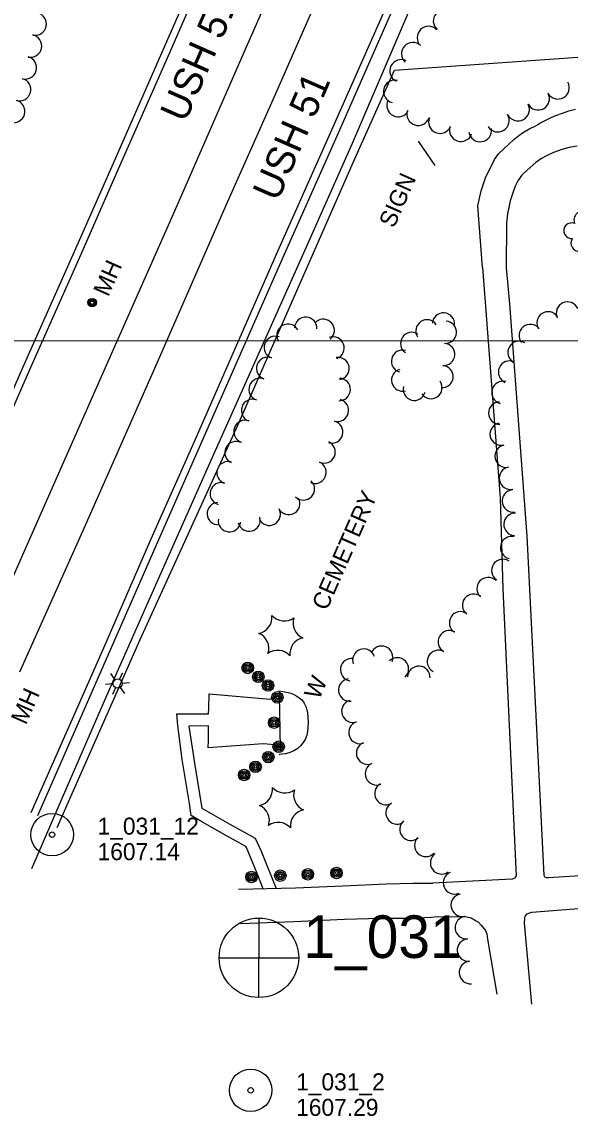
# Model space of a CAD drawing. Extents: x 189384 to 193282, y 256970 to 260388.
# Drawn here: x 190295.2 to 190488.3, y 257237.9 to 257623.7 of the extents above; entities that cross this region are included whole.
import ezdxf

# ---------------------------------------------------------------- set-up
doc = ezdxf.new("R2010")
doc.units = 0
for name, color, linetype in [('E_BMGRD', 7, 'Continuous'), ('E_DRN_Grate', 7, 'Continuous'), ('E_DWY', 7, 'Continuous'), ('E_LAND_Vegetation', 7, 'Continuous'), ('E_MAP_GridLines', 7, 'Continuous'), ('E_MAP_Limits', 7, 'Continuous'), ('E_MAP_PassPoints', 7, 'Continuous'), ('E_MISCPROP', 7, 'Continuous'), ('E_MISCPROP_Railing', 7, 'Continuous'), ('E_PATH_Sidewalk', 7, 'Continuous'), ('E_RDWY', 7, 'Continuous'), ('E_RDWY_Name', 7, 'Continuous')]:
    doc.layers.add(name, color=color, linetype=linetype)

# ---------------------------------------------------------------- blocks, each defined once
blk = doc.blocks.new('PP_8')
at = {"layer": 'E_MAP_PassPoints'}
for radius in [7.5, 0.96]:
    blk.add_circle((0, 0), radius, dxfattribs=at)
blk = doc.blocks.new('PHOTOC')
at = {"layer": 'E_MAP_Limits'}
for p, q in [((0.12, 14.06), (0.06, -13.8)), ((-13.79, 0.03), (14.12, 0.01))]:
    blk.add_line(p, q, dxfattribs=at)
blk.add_circle((0.17, 0.03), 14, dxfattribs=at)
blk = doc.blocks.new('CEM')
at = {"layer": 'E_BMGRD'}
blk.add_text('CEMETERY', height=6, rotation=0.0001, dxfattribs=at).set_placement((-22.99, -3.18))
blk = doc.blocks.new('WAL')
at = {"layer": 'E_MISCPROP_Railing'}
blk.add_text('W', height=6, rotation=360, dxfattribs=at).set_placement((-2.3, -3.01))
blk = doc.blocks.new('POLE')
at = {"layer": 'E_MISCPROP'}
for radius in [2.02, 1.51, 1.01, 0.504]:
    blk.add_circle((0.03, -0.09), radius, dxfattribs=at)
blk = doc.blocks.new('MHO_1')
at = {"layer": 'E_DRN_Grate'}
for centre, radius in [((0.04, -0.06), 1.5), ((0.04, -0.06), 1.22), ((0.04, -0.07), 0.968), ((0.01, -0.08), 0.605)]:
    blk.add_circle(centre, radius, dxfattribs=at)
blk = doc.blocks.new('LTP_11')
at = {"layer": 'E_MISCPROP'}
for p, q in [((-1.64, 0.07), (-4.24, 0.14)), ((-0.8, 1.43), (-2, 3.73)), ((0.9, 1.42), (2.27, 3.65)), ((-0.88, -1.42), (-2.24, -3.61)), ((0.76, -1.47), (2, -3.65)), ((1.64, -0.02), (4.16, -0.09))]:
    blk.add_line(p, q, dxfattribs=at)
blk.add_circle((0, 0), 1.64, dxfattribs=at)
blk = doc.blocks.new('SIGN_8')
at = {"layer": 'E_MISCPROP'}
blk.add_text('SIGN', height=6, rotation=0.0002, dxfattribs=at).set_placement((-9.61, -3.01))
blk = doc.blocks.new('TREE_3')
at = {"layer": 'E_LAND_Vegetation'}
for centre, radius, start, end in [((-1.47, 4.28), 2.78, 1.3945, 209.1675), ((3.57, 2.42), 2.97, 278.4236, 139.6575), ((-4.47, 0.2), 2.78, 78.0715, 279.0825), ((-2.01, -4.2), 2.61, 140.7796, 358.7122), ((3.46, -3.43), 2.97, 196.0744, 79.0477)]:
    blk.add_arc(centre, radius, start, end, dxfattribs=at)
blk = doc.blocks.new('PINEL')
at = {"layer": 'E_LAND_Vegetation'}
for centre, start, end in [((-8.23, 7.26), 275.2112, 0.9761), ((2.17, 10.66), 215.2112, 300.9761), ((10.31, 3.35), 155.2112, 240.9761), ((-10.49, -3.45), 335.2112, 60.9761), ((8.05, -7.36), 95.2112, 180.9761), ((-2.35, -10.75), 35.2112, 120.9761)]:
    blk.add_arc(centre, 5.72, start, end, dxfattribs=at)

msp = doc.modelspace()

# ---------------------------------------------------------------- linework, layer by layer
at = {"layer": 'E_DWY'}
for points in [[(190307.65, 257339.7), (190336.95, 257405.99), (190371.25, 257481.51), (190412.4, 257575.11), (190426.44, 257606.63), (190736.05, 257628.66), (190837.56, 257638.62), (191029.69, 257654.26)], [(190457.48, 257537.03), (190455.79, 257558.86), (190457.06, 257564.15), (190458.56, 257568.63), (190461.68, 257575.18), (190463.17, 257577.14), (190468.54, 257582.25), (190470.23, 257583.55), (190471.59, 257584.56), (190474.12, 257586.03), (190475.84, 257586.81), (190476.63, 257587.3), (190477.72, 257587.94), (190479.51, 257588.94), (190481.22, 257589.77), (190482.91, 257590.5), (190485.63, 257591.48), (190487.88, 257592.34), (190490.23, 257592.92)], [(190490.8, 257579.87), (190488, 257579.42), (190485.39, 257578.67), (190482.5, 257577.63), (190479.98, 257576.43), (190478.24, 257575.49), (190476.27, 257574.07), (190472.15, 257570.49), (190471.16, 257569.47), (190470.46, 257568.48), (190469.97, 257567.68), (190468.96, 257565.73), (190468.01, 257563.03), (190467.26, 257560.54), (190466.71, 257558.23), (190466.31, 257555.95), (190466.07, 257553.88), (190465.9, 257552.65), (190465.78, 257536.97)], [(190457.48, 257537.03), (190463.71, 257455.89), (190464.64, 257423.78), (190469.29, 257322.59), (190469.05, 257322.23), (190468.71, 257321.86), (190468.3, 257321.58), (190467.97, 257321.45), (190440.02, 257320.03)], [(190465.78, 257536.97), (190467.02, 257524.23), (190473.06, 257442.37), (190479.12, 257322.87), (190479.29, 257322.36), (190479.54, 257322.11), (190479.86, 257322.08), (190480.25, 257322.06), (190480.78, 257322.01), (190512.77, 257323.99)], [(190371.51, 257317.92), (190391.66, 257318.35), (190408.25, 257319.12), (190423.64, 257319.82), (190432.93, 257320.04), (190440.02, 257320.03)], [(190474.86, 257277.41), (190472.3, 257305.98), (190472.39, 257307.74), (190472.53, 257308.47), (190473.17, 257309.2), (190474.21, 257309.64), (190474.87, 257309.87), (190495.81, 257311.42)], [(190372.26, 257305.87), (190391.08, 257306.56), (190408.85, 257307.39)], [(190408.85, 257307.39), (190421.59, 257307.71), (190432.22, 257307.75), (190439.44, 257308.01), (190441.6, 257308.25)], [(190441.58, 257308.24), (190449.96, 257308.3), (190451.94, 257308.13), (190453.45, 257307.86), (190454.99, 257306.94), (190456.1, 257306.25), (190457.03, 257305.3), (190458.53, 257303.32), (190459.04, 257302.15), (190459.23, 257300.34), (190462.51, 257280.9)]]:
    msp.add_lwpolyline(points, dxfattribs=at)
at = {"layer": 'E_LAND_Vegetation'}
for centre, radius, start, end in [((190444.16, 257623.99), 4.01, 49.4292, 229.4139), ((190299.87, 257622.93), 3.99, 258.5278, 78.5124), ((190438.47, 257618.09), 4.01, 44.6194, 224.604), ((190298.25, 257615.15), 3.99, 257.7676, 77.7523), ((190432.96, 257612.39), 4.01, 47.0397, 227.0244), ((190296.43, 257607.49), 3.99, 255.1576, 75.1423), ((190428.85, 257606.35), 4.01, 64.0125, 243.9972), ((190294.39, 257599.78), 3.99, 255.1576, 75.1423), ((190426.61, 257599.14), 4.01, 76.0062, 255.9909), ((190484.04, 257600.46), 4.01, 209.2062, 29.1908), ((190477.06, 257596.59), 4.01, 208.3495, 28.3342), ((190292.31, 257592.11), 3.99, 254.5256, 74.5103), ((190427.78, 257594.2), 4.01, 153.0039, 332.9886), ((190470, 257592.78), 4.01, 208.3495, 28.3342), ((190434.84, 257591.16), 4.01, 161.8069, 341.7915), ((190442.5, 257588.36), 4.01, 157.7411, 337.7258), ((190462.88, 257588.85), 4.01, 211.7721, 31.7568), ((190449.87, 257585.51), 4.01, 160.9685, 340.9532), ((190456.65, 257585.41), 4.01, 188.9113, 8.896), ((190487.42, 257520.98), 3.96, 24.9631, 204.9478), ((190395.22, 257515.65), 3.94, 356.9463, 176.931), ((190443.75, 257517.16), 3.92, 355.933, 175.9176), ((190480.6, 257517.53), 3.96, 32.5768, 212.5615), ((190388.97, 257513.23), 3.94, 27.6729, 207.6575), ((190401.38, 257514.91), 3.94, 309.3236, 129.3082), ((190437.91, 257514.74), 3.92, 33.4141, 213.3987), ((190444.4, 257514.25), 3.92, 265.7356, 85.7203), ((190474.34, 257513.09), 3.96, 39.2218, 219.2065), ((190384.49, 257508.91), 3.94, 70.1837, 250.1684), ((190404.83, 257508.72), 3.94, 290.2546, 110.2393), ((190432.52, 257510.31), 3.92, 55.724, 235.7086), ((190429.29, 257504.03), 3.92, 74.8901, 254.8748), ((190443.81, 257506.43), 3.92, 265.7356, 85.7203), ((190470.35, 257507.14), 3.96, 59.5352, 239.5198), ((190381.82, 257501.5), 3.94, 70.1837, 250.1684), ((190406.6, 257501.46), 3.94, 279.8712, 99.8558), ((190467.03, 257500.2), 3.96, 65.7729, 245.7575), ((190429.36, 257497.39), 3.92, 104.9791, 284.9637), ((190443.23, 257498.61), 3.92, 265.7356, 85.7203), ((190379.15, 257494.09), 3.94, 70.1837, 250.1684), ((190407, 257494.07), 3.94, 267.5907, 87.5754), ((190439.34, 257494.75), 3.92, 214.3449, 34.3296), ((190464.68, 257493.01), 3.96, 75.0733, 255.058), ((190433.47, 257494.13), 3.92, 165.193, 345.1777), ((190376.48, 257486.68), 3.94, 70.1837, 250.1684), ((190406.4, 257486.7), 3.94, 255.1624, 75.1471), ((190463.54, 257485.78), 3.96, 90.2963, 270.281), ((190373.81, 257479.27), 3.94, 70.1837, 250.1684), ((190404.38, 257479.08), 3.94, 255.1624, 75.1471), ((190464.07, 257478.36), 3.96, 102.704, 282.6887), ((190370.64, 257471.82), 3.94, 63.7403, 243.725), ((190401.7, 257472.06), 3.94, 245.8983, 65.8829), ((190465.81, 257470.57), 3.96, 101.1822, 281.1669), ((190367.86, 257464.75), 3.94, 71.6053, 251.5899), ((190398.48, 257464.87), 3.94, 245.8983, 65.8829), ((190467.35, 257462.79), 3.96, 101.1822, 281.1669), ((190394.39, 257459.01), 3.94, 225.7166, 45.7013), ((190365.47, 257457.35), 3.94, 74.2572, 254.2419), ((190468.37, 257454.76), 3.96, 96.5899, 276.5745), ((190364.44, 257450.33), 3.94, 93.2622, 273.2469), ((190389.26, 257453.89), 3.94, 208.6708, 28.6554), ((190382.35, 257450.11), 3.94, 208.6708, 28.6554), ((190468.95, 257446.52), 3.96, 86.94, 266.9246), ((190368.34, 257447.82), 3.94, 172.6951, 352.6798), ((190375.26, 257448.06), 3.94, 195.1824, 15.1671), ((190467.75, 257438.35), 3.96, 77.0253, 257.0099), ((190464.65, 257430.3), 3.96, 56.7802, 236.7649), ((190459.46, 257423.87), 3.96, 46.7976, 226.7823), ((190454.38, 257418.01), 3.96, 51.6105, 231.5952), ((190449.77, 257411.82), 3.96, 57.2338, 237.2185), ((190445.79, 257405.14), 3.96, 61.1189, 241.1036), ((190421.95, 257399.67), 3.96, 338.1776, 158.1622), ((190415.7, 257398.66), 3.96, 19.6155, 199.6002), ((190441.96, 257398.2), 3.96, 61.3981, 241.3828), ((190411.4, 257395.33), 3.96, 80.5298, 260.5145), ((190427.49, 257395.55), 3.96, 314.2426, 134.2272), ((190435.05, 257392.6), 3.96, 356.8868, 176.8715), ((190410.7, 257388.14), 3.96, 98.2019, 278.1866), ((190411.82, 257380.66), 3.96, 108.2608, 288.2455), ((190414.32, 257373.17), 3.96, 109.1472, 289.1319), ((190417.02, 257365.86), 3.96, 112.7782, 292.7628), ((190420.13, 257358.6), 3.96, 113.6871, 293.6718), ((190423.45, 257351.64), 3.96, 119.3556, 299.3403), ((190427.4, 257344.82), 3.96, 120.7747, 300.7594), ((190432.28, 257339.07), 3.96, 130.7458, 310.7305), ((190437.49, 257333.37), 3.96, 136.2159, 316.2006), ((190443.08, 257327.23), 3.96, 125.4242, 305.4089), ((190447.6, 257320.18), 3.96, 112.064, 292.0487), ((190450.31, 257312.31), 3.96, 100.0324, 280.017), ((190451.79, 257304.38), 3.96, 96.1611, 276.1457), ((190452.54, 257296.45), 3.96, 95.165, 275.1497), ((190453.25, 257288.56), 3.96, 95.165, 275.1497)]:
    msp.add_arc(centre, radius, start, end, dxfattribs=at)
at = {"layer": 'E_MAP_GridLines'}
for p in [(189647.76, 257510.74), (190147.76, 257511.09)]:
    msp.add_line(p, (191647.75, 257512.16), dxfattribs=at)
at = {"layer": 'E_MISCPROP'}
msp.add_line((190440.76, 257573.08), (190434.99, 257581.64), dxfattribs=at)
at = {"layer": 'E_MISCPROP_Railing'}
msp.add_lwpolyline([(190385.72, 257387.81), (190387.32, 257387.65), (190389.02, 257387.27), (190389.98, 257386.97), (190391.08, 257386.53), (190392.12, 257385.98), (190392.93, 257385.37), (190393.79, 257384.62), (190394.64, 257383.46), (190395.24, 257382.29), (190395.61, 257381.11), (190395.83, 257380.06), (190396, 257378.54), (190396.04, 257376.83), (190396.01, 257375.1), (190395.88, 257373.55), (190395.59, 257372.26), (190394.99, 257370.69), (190394.35, 257369.6), (190393.36, 257368.42), (190392.39, 257367.51), (190390.98, 257366.67), (190389.36, 257366), (190388.05, 257365.66), (190386.88, 257365.5), (190386, 257365.37), (190385.86, 257365.34)], dxfattribs=at)
at = {"layer": 'E_PATH_Sidewalk'}
for points in [[(190298.77, 257325.23), (190309.52, 257350.29), (190325.17, 257386.26), (190343.36, 257427.37), (190362.39, 257470.22), (190394.6, 257542.28), (190411.69, 257580.96), (190438.45, 257643.57), (190449.34, 257668.76), (190455.73, 257682.97)], [(190380.24, 257318.11), (190378.13, 257323.51), (190374.4, 257332.6), (190374.13, 257332.93), (190367.5, 257336.59), (190358.85, 257341.57), (190354.82, 257343.9), (190354.25, 257348.12), (190351.69, 257363.7), (190350.21, 257375.6), (190349.83, 257379.72), (190360.97, 257379.75), (190361.09, 257381.68), (190361.15, 257386.79), (190382.65, 257384.92), (190385.83, 257386.09), (190386.22, 257367.83), (190384.5, 257368.75), (190384.29, 257368.81), (190380.28, 257369.12), (190360.82, 257367.78), (190360.96, 257370.34), (190360.94, 257375.54), (190354.03, 257375.42), (190356.18, 257361.65), (190358.66, 257346.47), (190368.53, 257340.89), (190377.36, 257335.86), (190379.48, 257331.37), (190384.79, 257318.21)]]:
    msp.add_lwpolyline(points, dxfattribs=at)
at = {"layer": 'E_RDWY'}
for points in [[(190639.31, 258218.07), (190609.41, 258149.39), (190580.27, 258083.06), (190547.78, 258009.13), (190519.09, 257944.03), (190494.25, 257887.28), (190465.55, 257822.08), (190442.19, 257769.07), (190419.9, 257718.5), (190394.49, 257660.93), (190374.24, 257614.8), (190349, 257556.99), (190323.12, 257498.57), (190298.43, 257442.39), (190276.94, 257393.85), (190259.86, 257355.22)], [(190647.06, 258194.52), (190624.13, 258142.92), (190594.92, 258076.29), (190570.69, 258021.28), (190551.11, 257977.35), (190533.78, 257937.86), (190511.8, 257887.72), (190488.43, 257834.81), (190463.86, 257779), (190437.37, 257718.32), (190410.84, 257658.32), (190384.1, 257597.28), (190367.03, 257558.94), (190342.84, 257503.57), (190317.05, 257445.11), (190294.43, 257394.4)], [(190250.08, 257392.44), (190265, 257426.05), (190280.63, 257461.47), (190298.01, 257501.1), (190315.61, 257540.66), (190329.32, 257571.82), (190346.52, 257610.97), (190369.12, 257662.7), (190389.76, 257709.75), (190408.17, 257751.62), (190431.5, 257804.24), (190444.63, 257834.42), (190462.73, 257875.09), (190477.51, 257908.64), (190486.34, 257929.3)], [(190262.71, 257427.06), (190278.34, 257462.48), (190295.73, 257502.11), (190313.33, 257541.67), (190327.03, 257572.83), (190344.23, 257611.97), (190366.83, 257663.7), (190387.47, 257710.75), (190405.88, 257752.63), (190429.21, 257805.24), (190442.34, 257835.43), (190460.44, 257876.1), (190475.22, 257909.64), (190484.04, 257930.29)], [(190298.55, 257344.93), (190324.04, 257403.04), (190340.35, 257440.33), (190356.36, 257476.6), (190385.44, 257542.83), (190404.46, 257585.57), (190428.47, 257640.15), (190447.87, 257683.88)], [(190300.84, 257343.92), (190326.33, 257402.04), (190342.64, 257439.32), (190358.64, 257475.59), (190387.73, 257541.82), (190406.75, 257584.56), (190430.76, 257639.14), (190450.16, 257682.87)]]:
    msp.add_lwpolyline(points, dxfattribs=at)

# ---------------------------------------------------------------- block references
at = {"layer": 'E_BMGRD', "xscale": 1.0000017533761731, "yscale": 1.0000017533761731, "rotation": 66.23800861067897}
msp.add_blockref('CEM', (190408.98, 257438.14), dxfattribs=at)
at = {"layer": 'E_DRN_Grate', "rotation": 66.02695272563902}
msp.add_blockref('MHO_1', (190319.92, 257524.68), dxfattribs=at)
at = {"layer": 'E_LAND_Vegetation'}
for name, p, rotation in [('TREE_3', (190493.42, 257549.64), 66.02694963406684), ('PINEL', (190386.47, 257407.41), 66.02695153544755), ('PINEL', (190386.66, 257346.78), 66.02695152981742)]:
    msp.add_blockref(name, p, dxfattribs=dict(at, rotation=rotation))
at = {"layer": 'E_MAP_Limits', "rotation": -9.923642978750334e-05}
msp.add_blockref('PHOTOC', (190378.56, 257293.72), dxfattribs=at)
at = {"layer": 'E_MAP_PassPoints'}
for p, rotation in [((190305.89, 257337.16), -9.793963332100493e-05), ((190375.83, 257247.03), -9.918925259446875e-05)]:
    msp.add_blockref('PP_8', p, dxfattribs=dict(at, rotation=rotation))
at = {"layer": 'E_MISCPROP'}
for name, p, rotation in [('SIGN_8', (190427.42, 257560.65), 66.02695081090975), ('POLE', (190374.69, 257395.93), 66.07484673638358), ('LTP_11', (190328.96, 257390.42), 66.0269525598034), ('POLE', (190378.41, 257392.8), 66.07484666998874), ('POLE', (190381.84, 257389.75), 66.07484660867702), ('POLE', (190385.12, 257385.55), 66.07484655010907), ('POLE', (190383.99, 257376.64), 66.07484656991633), ('POLE', (190385.58, 257368.16), 66.07484654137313), ('POLE', (190381.95, 257364.51), 66.07484660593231), ('POLE', (190377.41, 257361.06), 66.07484668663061), ('POLE', (190373.42, 257358.18), 66.07484675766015), ('POLE', (190376.01, 257322.22), 66.07484671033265), ('POLE', (190386.17, 257322.72), 66.07484652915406), ('POLE', (190395.85, 257323.17), 66.07484635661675), ('POLE', (190405.94, 257323.66), 66.07484617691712)]:
    msp.add_blockref(name, p, dxfattribs=dict(at, rotation=rotation))
at = {"layer": 'E_MISCPROP_Railing', "rotation": 66.3595082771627}
msp.add_blockref('WAL', (190398.09, 257387.72), dxfattribs=at)

# ---------------------------------------------------------------- texts
at = {"layer": 'E_DRN_Grate'}
for p in [(190325.64, 257526.5), (190296.61, 257375.6)]:
    msp.add_text('MH', height=6, rotation=66.027, dxfattribs=at).set_placement(p)
at = {"layer": 'E_MAP_Limits'}
msp.add_text('1_031', height=15, rotation=0, dxfattribs=at).set_placement((190394.39, 257293.69))
at = {"layer": 'E_MAP_PassPoints'}
for s, p in [('1_031_12', (190321.89, 257337.16)), ('1607.14', (190321.89, 257328.16)), ('1_031_2', (190391.83, 257247.02)), ('1607.29', (190391.83, 257238.02))]:
    msp.add_text(s, height=6, rotation=0, dxfattribs=at).set_placement(p)
at = {"layer": 'E_RDWY_Name'}
for rotation, p in [(66.2195, (190352.74, 257587.78)), (66.4032, (190385.35, 257559.96))]:
    msp.add_text('USH 51', height=10, rotation=rotation, dxfattribs=at).set_placement(p)

doc.saveas('drawing.dxf')
